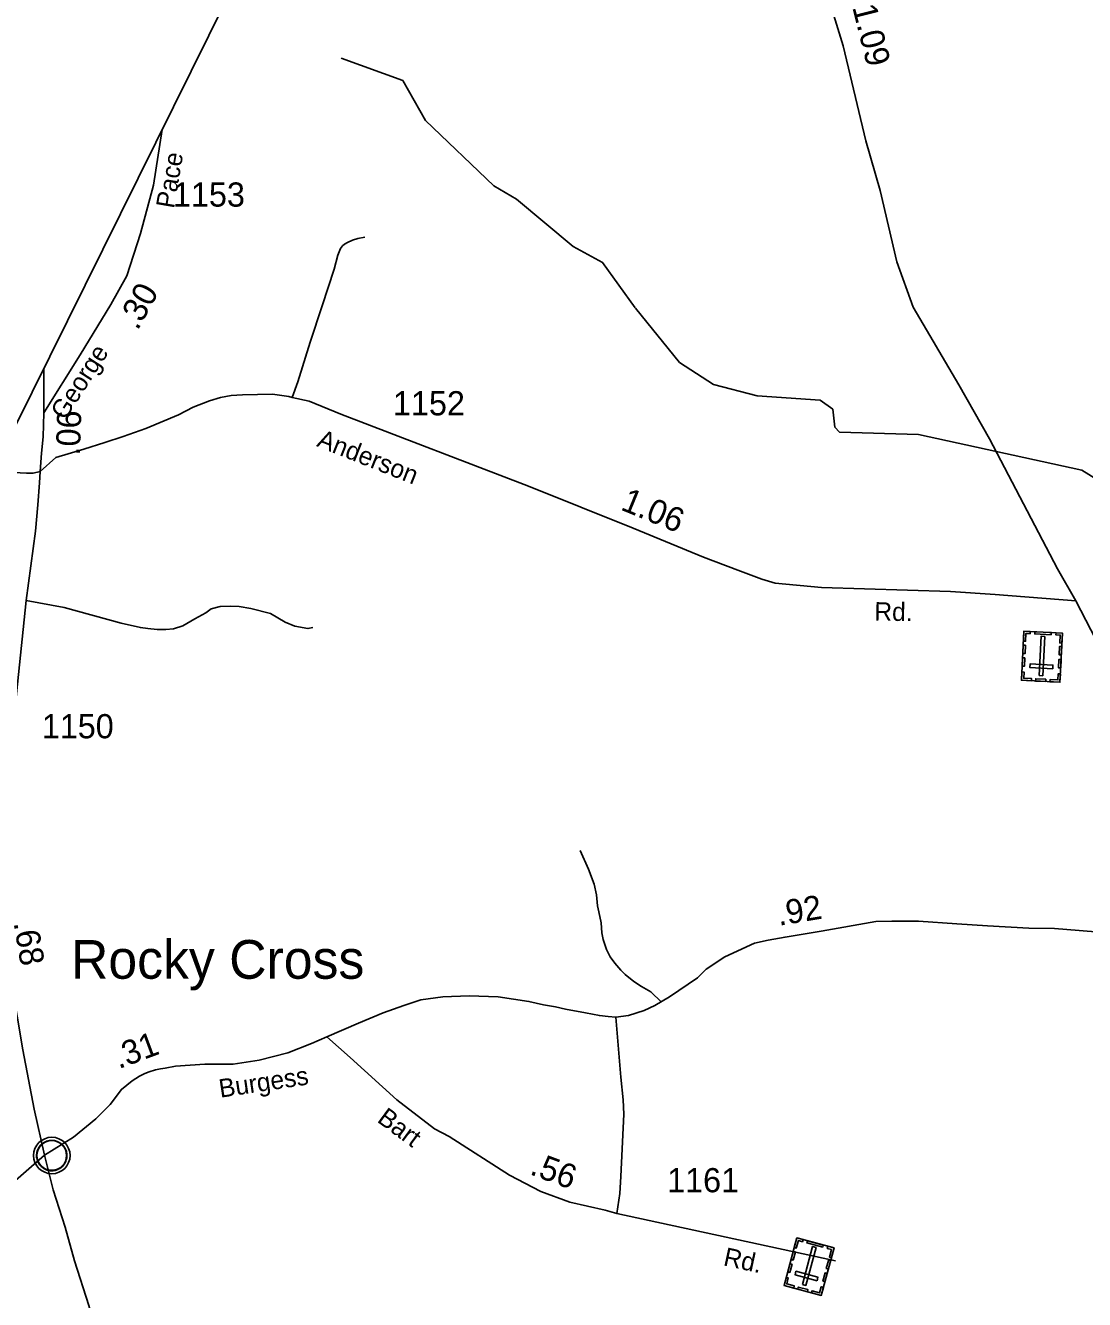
# Model space of a CAD drawing. Extents: x 2220236 to 2384410, y 720751 to 894131.
# Drawn here: x 2230421 to 2235894, y 769263 to 775846 of the extents above; entities that cross this region are included whole.
import ezdxf

# ---------------------------------------------------------------- set-up
doc = ezdxf.new("R2010")
doc.units = 0
for name, color, linetype in [('Exist Boundary Political CountyLine', 7, 'Continuous'), ('Exist Civil Demographics Community CELL', 7, 'Continuous'), ('Exist Civil Demographics Community Label', 7, 'Continuous'), ('Exist Cultural Cemetery CELL', 7, 'Continuous'), ('Exist Hydrographic Creek Single Shore', 7, 'Continuous'), ('Exist Road Non-System Type 51', 7, 'Continuous'), ('Exist Road Secondary Mileage Hundredths English Label', 7, 'Continuous'), ('Exist Road Secondary Type 51 Attributed', 7, 'Continuous'), ('Exist Road Secondary Type 51 Label', 7, 'Continuous'), ('Exist Road Secondary Type 51 Number Label', 7, 'Continuous')]:
    doc.layers.add(name, color=color, linetype=linetype)

msp = doc.modelspace()

# ---------------------------------------------------------------- linework, layer by layer
at = {"layer": 'Exist Boundary Political CountyLine'}
msp.add_lwpolyline([(2293117.8, 894131.3), (2291903.9, 891776.4), (2258821.6, 829664.6), (2255410.5, 823324), (2242088.6, 797598.7), (2231459.6, 775980.5), (2225010.8, 762953.2), (2220575.6, 753519.5)], dxfattribs=at)
at = {"layer": 'Exist Civil Demographics Community CELL'}
msp.add_lwpolyline([(2230479.8, 770019.3), (2230480.8, 770024.8), (2230482.5, 770031.4), (2230485.5, 770038.6), (2230488.4, 770044.4), (2230491.7, 770050.1), (2230495.5, 770055.2), (2230499.5, 770059.6), (2230504, 770064.2), (2230509.6, 770068.8), (2230515, 770072.4), (2230519.9, 770075.3), (2230524.9, 770077.8), (2230530.4, 770080.1), (2230536, 770081.9), (2230540.4, 770083), (2230545.2, 770083.8), (2230549.3, 770084.5), (2230555.7, 770084.7), (2230560.1, 770084.6), (2230565.8, 770084.4), (2230570.7, 770083.7), (2230575.6, 770082.7), (2230580.6, 770081.3), (2230585.8, 770079.3), (2230592.4, 770076.4), (2230598.7, 770072.9), (2230603.8, 770069.4), (2230608.9, 770065.3), (2230612.2, 770062.2), (2230616.4, 770057.8), (2230620.2, 770053.1), (2230623.3, 770048.5), (2230626.4, 770043.5), (2230628.9, 770038.4), (2230630.9, 770033.4), (2230632.5, 770028.3), (2230633.8, 770023.8), (2230634.9, 770017.7), (2230635.5, 770013), (2230635.7, 770007), (2230635.6, 770001.2), (2230635, 769995.5), (2230634, 769990), (2230632.4, 769983.9), (2230630.5, 769978), (2230628.2, 769973), (2230625.1, 769967), (2230621.8, 769961.7), (2230618.3, 769957), (2230614.1, 769952.2), (2230608.8, 769947.3), (2230603.8, 769943.1), (2230598.8, 769939.7), (2230594.5, 769937.2), (2230587.7, 769934), (2230580.5, 769931.2), (2230574.6, 769929.8), (2230568, 769928.5), (2230563.5, 769928), (2230559, 769927.7), (2230553.5, 769927.7), (2230549.2, 769928.2), (2230543.5, 769928.9), (2230537.6, 769930.2), (2230533, 769931.5), (2230527.9, 769933.4), (2230523.3, 769935.4), (2230519.4, 769937.6), (2230512.5, 769941.7), (2230507, 769946), (2230502.1, 769950.4), (2230497.6, 769955.3), (2230494.4, 769959.3), (2230491.4, 769963.4), (2230487.3, 769970.5), (2230485.6, 769974.1), (2230483.9, 769978.1), (2230481.3, 769986.3), (2230479.8, 769993.3), (2230479.1, 769998.5), (2230478.8, 770004.8), (2230478.7, 770009.5), (2230479.3, 770016)], close=True, dxfattribs=at)
for centre, radius in [((2230557.4, 770006.8), 94.3), ((2230557.1, 770007.1), 76.7)]:
    msp.add_circle(centre, radius, dxfattribs=at)
at = {"layer": 'Exist Cultural Cemetery CELL'}
for points in [[(2235767, 772452.5), (2235568.2, 772462.3), (2235580.7, 772716.6), (2235779.6, 772706.8)], [(2235613.8, 772715), (2235613.3, 772703.5), (2235591.3, 772704.6), (2235589.3, 772664.2), (2235578.2, 772664.7), (2235580.7, 772716.6)], [(2235721.6, 772698.1), (2235636.9, 772702.3), (2235637.4, 772713.7), (2235722.2, 772709.5)], [(2235659.6, 772487.1), (2235678.2, 772486.2), (2235688.2, 772688.7), (2235669.6, 772689.6)], [(2235746.5, 772708.4), (2235746, 772696.9), (2235768, 772695.8), (2235766, 772655.4), (2235777.1, 772654.9), (2235779.6, 772706.7)], [(2235588.5, 772643.8), (2235586.4, 772600.6), (2235575, 772601.1), (2235577.2, 772644.4)], [(2235776.2, 772636.9), (2235774, 772593.7), (2235762.7, 772594.2), (2235764.8, 772637.5)], [(2235585.3, 772578), (2235583.1, 772534.7), (2235571.8, 772535.3), (2235573.9, 772578.6)], [(2235729.6, 772522.4), (2235730.6, 772541.1), (2235612.9, 772546.9), (2235612, 772528.2)], [(2235772.8, 772569.8), (2235770.7, 772526.5), (2235759.3, 772527.1), (2235761.5, 772570.3)], [(2235570.3, 772505.6), (2235581.6, 772505), (2235580, 772472.9), (2235620.5, 772470.9), (2235620, 772459.8), (2235568.1, 772462.3)], [(2235693.1, 772456.1), (2235641.3, 772458.7), (2235641.9, 772470.1), (2235693.6, 772467.5)], [(2235769.2, 772495.7), (2235757.8, 772496.3), (2235756.3, 772464.1), (2235715.7, 772466.1), (2235715.2, 772455), (2235767, 772452.5)], [(2234533.3, 769283.4), (2234341.1, 769335.2), (2234407.3, 769581.1), (2234599.6, 769529.3)], [(2234439.3, 769572.5), (2234436.3, 769561.4), (2234415.1, 769567.1), (2234404.6, 769528.1), (2234393.8, 769531), (2234407.3, 769581.1)], [(2234541.1, 769533.2), (2234459.2, 769555.2), (2234462.1, 769566.2), (2234544.1, 769544.2)], [(2234399.5, 769508.4), (2234388.2, 769466.5), (2234377.2, 769469.5), (2234388.5, 769511.3)], [(2234435.7, 769340.1), (2234453.7, 769335.2), (2234506.5, 769531), (2234488.4, 769535.9)], [(2234567.6, 769537.8), (2234564.6, 769526.7), (2234585.9, 769521), (2234575.3, 769482), (2234586.1, 769479.1), (2234599.6, 769529.2)], [(2234382.3, 769444.7), (2234371, 769402.9), (2234360.1, 769405.9), (2234371.3, 769447.7)], [(2234581.4, 769461.7), (2234570.1, 769419.9), (2234559.1, 769422.9), (2234570.4, 769464.7)], [(2234352.3, 769377.1), (2234363.2, 769374.2), (2234354.9, 769343.1), (2234394, 769332.5), (2234391.1, 769321.8), (2234341, 769335.3)], [(2234511.6, 769359.8), (2234516.5, 769377.8), (2234402.8, 769408.4), (2234397.9, 769390.4)], [(2234563.9, 769396.8), (2234552.6, 769355), (2234541.6, 769358), (2234552.9, 769399.8)], [(2234461.8, 769302.7), (2234411.7, 769316.2), (2234414.7, 769327.2), (2234464.7, 769313.7)], [(2234544.6, 769325.2), (2234533.6, 769328.2), (2234525.2, 769297.1), (2234486.1, 769307.7), (2234483.2, 769296.9), (2234533.3, 769283.4)]]:
    msp.add_lwpolyline(points, close=True, dxfattribs=at)
at = {"layer": 'Exist Hydrographic Creek Single Shore'}
for points in [[(2233572, 774387), (2233403.1, 774622), (2233252.2, 774703.8), (2232959.1, 774949.3), (2232841, 775017.4), (2232489.2, 775355.9), (2232371.1, 775561.7), (2232053, 775676.5)], [(2236038, 773449.3), (2235879.1, 773547.6), (2235036.1, 773732.2), (2234628.1, 773744), (2234603.1, 773770.7), (2234594, 773862.8), (2234527, 773910.1), (2234202.2, 773933.1), (2233976, 773990.2), (2233801.1, 774105.4), (2233573.4, 774385.3)]]:
    msp.add_lwpolyline(points, dxfattribs=at)
at = {"layer": 'Exist Road Non-System Type 51'}
for points in [[(2231798.7, 773924.5), (2231828.8, 774005.4), (2231892.7, 774208.9), (2231954.7, 774396.9), (2232016.7, 774586.9), (2232036.1, 774658.6), (2232049.6, 774693.5), (2232059.3, 774707.1), (2232069, 774716.8), (2232084.5, 774724.5), (2232111.6, 774736.2), (2232138.8, 774745.8), (2232175.6, 774751.7)], [(2230425.5, 772875.5), (2230620.4, 772839), (2230915.1, 772757.4), (2231015.6, 772734.9), (2231053.7, 772729.7), (2231102.2, 772724.5), (2231147.3, 772724.5), (2231185.4, 772728), (2231234, 772743.6), (2231296.4, 772780), (2231353.6, 772811.2), (2231381.3, 772832), (2231428.1, 772844.2), (2231481.8, 772845.9), (2231525.2, 772844.2), (2231585.8, 772833.8), (2231688.1, 772807.7), (2231762.6, 772762.6), (2231812.9, 772741.8), (2231880.5, 772729.7), (2231906.5, 772734.9)], [(2233288.4, 771582.5), (2233331, 771487.1), (2233359.6, 771409.3), (2233372, 771353.5), (2233376.5, 771297.4), (2233384.8, 771265.4), (2233395.3, 771209.6), (2233399.6, 771157.8), (2233405.9, 771123.8), (2233424.4, 771071.9), (2233442.6, 771034.1), (2233466.9, 771000.4), (2233497.2, 770964.6), (2233519.3, 770942.7), (2233565.8, 770905.2), (2233603.8, 770879.4), (2233652, 770851.8), (2233707.3, 770799.4)], [(2233471.6, 770721.3), (2233497.6, 770410.9), (2233509.7, 770294.7), (2233513.2, 770220.1), (2233497.9, 769899.1), (2233492.7, 769811), (2233477.5, 769706.9)]]:
    msp.add_lwpolyline(points, dxfattribs=at)
at = {"layer": 'Exist Road Secondary Type 51 Attributed'}
for p, q in [((2230516, 773843.7), (2230516.1, 774074.4)), ((2230519.9, 770008.5), (2230316.4, 769831.6))]:
    msp.add_line(p, q, dxfattribs=at)
for points in [[(2234516.6, 776167.7), (2234646.7, 775740.6), (2234764.4, 775250), (2234838.5, 774992.6), (2234924.2, 774624.7), (2235008.7, 774391.4), (2235243.7, 773989.5), (2235402, 773710.9), (2235753.4, 773038.1), (2235849.5, 772873.6)], [(2230516, 773843.7), (2230704.5, 774144), (2230862.2, 774403.5), (2230944.8, 774552.8), (2231015.7, 774770.5), (2231083.3, 775021.6), (2231126.9, 775308.3)], [(2235849.5, 772873.6), (2235431.8, 772906.6), (2235201.3, 772920.5), (2234534.6, 772942.2), (2234294.8, 772963.8), (2234227.2, 772984.6), (2234102.5, 773031.5), (2233925.7, 773099.1), (2233561.7, 773248.3), (2233020.9, 773465), (2232050.5, 773837.6), (2231887.4, 773905.6), (2231798.7, 773924.5), (2231781.7, 773928.1), (2231698.5, 773940.2), (2231542.5, 773936.8), (2231483.6, 773933.3), (2231429.8, 773922.9), (2231372.3, 773906), (2231287.7, 773874.3), (2231211.4, 773834.5), (2231042.8, 773763.2), (2230926.4, 773722.7), (2230832.2, 773691.8), (2230722.9, 773656), (2230578.8, 773614.2), (2230496.4, 773541.3)], [(2230496.4, 773541.3), (2230504.7, 773635.5), (2230512.2, 773719.8), (2230516, 773843.7)], [(2230496.4, 773541.3), (2230460.5, 773532.1), (2230427.1, 773532.1), (2230327.5, 773537.9), (2230251.4, 773539.8)], [(2230519.9, 770008.5), (2230466.2, 770246.1), (2230407, 770553.6), (2230320.8, 771063.9), (2230284.1, 771284.2), (2230284.1, 771362.6), (2230292.4, 771551.1), (2230330.8, 771946.6), (2230380, 772442.1), (2230425.5, 772875.5), (2230473, 773233.4), (2230484.3, 773369.8), (2230493.9, 773482.9), (2230496.4, 773541.3)], [(2235849.5, 772873.6), (2235952.3, 772673.9), (2236088.1, 772424.9), (2236208, 772186.1), (2236324, 771945.2), (2236431.9, 771698.1), (2236542.8, 771481), (2236600, 771354.4)], [(2236014.1, 771157.4), (2235738.6, 771179.2), (2235606.9, 771181.8), (2235392.3, 771193.3), (2235234.3, 771203.6), (2235036.6, 771217.1), (2234898.6, 771217.9), (2234814.8, 771215.6), (2234532.2, 771166.4), (2234346.6, 771135.5), (2234259.2, 771118.8), (2234188.5, 771103.4), (2234035.1, 771033.7), (2233938.9, 770969.5), (2233893.7, 770924.8), (2233749.8, 770825.9), (2233672.6, 770782.1), (2233617.5, 770755.3), (2233537.4, 770730), (2233471.6, 770721.3), (2233431.7, 770724.8), (2233387.2, 770729.7), (2233315.6, 770743.9), (2233211.6, 770763), (2233159.6, 770775.1), (2233098.9, 770785.5), (2233022.7, 770802.9), (2232863.4, 770825.9), (2232714.3, 770832.3), (2232578.2, 770825.9), (2232465.1, 770811.8), (2232377.1, 770781.5), (2232269.8, 770743.7), (2232142.7, 770691), (2231978.2, 770620.4)], [(2231978.2, 770620.4), (2231899.8, 770585.7), (2231776.5, 770536.9), (2231628.8, 770499.6), (2231493.9, 770479), (2231348.7, 770479), (2231196.2, 770468), (2231142.4, 770457.6), (2231119.6, 770454.3), (2231093.6, 770449.1), (2231060.7, 770438.7), (2231038.1, 770430), (2231010.4, 770416.1), (2230972.3, 770391.8), (2230916.8, 770348.5), (2230859.2, 770270.9), (2230784.7, 770196.4), (2230669.1, 770101.3), (2230519.9, 770008.5)], [(2231978.2, 770620.4), (2232099.5, 770513.5), (2232340.5, 770295.3), (2232534.5, 770145), (2232610.6, 770105.7), (2232922.1, 769904.5), (2233085.1, 769821.2), (2233234.1, 769765.7), (2233417.3, 769724.6), (2233477.5, 769706.9), (2234607, 769462.2)], [(2232000.6, 766032.7), (2231985.8, 766056.3), (2231957.4, 766104.1), (2231914.9, 766157.8), (2231868.6, 766209.3), (2231743.5, 766319.6), (2231622.2, 766441), (2231556.4, 766539.9), (2231515.2, 766658.3), (2231494.6, 766738.1), (2231446.5, 766977.6), (2231378, 767298.9), (2231337, 767426.5), (2231326.6, 767474.3), (2231206.2, 767743.5), (2231128.2, 767969), (2231063.1, 768174), (2230907, 768676.5), (2230835, 768935.9), (2230748.7, 769231.6), (2230674.7, 769462.2), (2230625.6, 769635.7), (2230564.4, 769829), (2230519.9, 770008.5)]]:
    msp.add_lwpolyline(points, dxfattribs=at)

# ---------------------------------------------------------------- texts
at = {"layer": 'Exist Civil Demographics Community Label'}
msp.add_text('Rocky Cross', height=200, dxfattribs=at).set_placement((2230656.5, 770920.1))
at = {"layer": 'Exist Road Secondary Mileage Hundredths English Label'}
for s, rotation, p in [('1.09', 284.05453, (2234693.3, 775941.1)), ('.30', 61.05422, (2231000.5, 774266.2)), ('.06', 88.2643, (2230703, 773622.8)), ('1.06', 337.71687, (2233491.5, 773345.6)), ('.92', 9.43017, (2234314.6, 771193.6)), ('.68', 279.59032, (2230359.6, 771209.3)), ('.31', 20.4107, (2230903, 770452.7)), ('.56', 339.57834, (2233022, 769911.4))]:
    msp.add_text(s, height=125, rotation=rotation, dxfattribs=at).set_placement(p)
at = {"layer": 'Exist Road Secondary Type 51 Label'}
for s, rotation, p in [('Pace', 80.46256, (2231188.8, 774897.1)), ('George', 57.15061, (2230624.9, 773802.2)), ('Anderson', 338.35708, (2231921.6, 773673.3)), ('Rd.', 358.89204, (2234806.9, 772771.6)), ('Burgess', 8.59559, (2231428.1, 770305)), ('Bart', 323.54178, (2232233.4, 770184.1)), ('Rd.', 347.77241, (2234023.1, 769440))]:
    msp.add_text(s, height=95, rotation=rotation, dxfattribs=at).set_placement(p)
at = {"layer": 'Exist Road Secondary Type 51 Number Label'}
for s, p in [('1153', (2231183.3, 774910)), ('1152', (2232320.2, 773831.5)), ('1150', (2230505.5, 772162.7)), ('1161', (2233736.8, 769816.8))]:
    msp.add_text(s, height=125, dxfattribs=at).set_placement(p)

doc.saveas('drawing.dxf')
